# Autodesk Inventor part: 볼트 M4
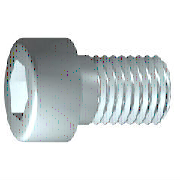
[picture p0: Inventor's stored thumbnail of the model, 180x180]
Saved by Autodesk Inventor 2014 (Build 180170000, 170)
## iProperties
IsCustomPart: 1
Created: 2012-02
Part Number: 볼트 M4
Material: 강철, 연강
Description: 6각머리 태핑 나사
Document SubType Name: Modeling
Standard: KS B 1003
Designer: mduedu
Standards Organization: KS
Language: ko-KR
Size Designation: M 4 x 10
Categories: <MemberInstance><Categories><Category DisplayName="조임쇠" InternalName="e4da775c-781d-43d5-af7c-5136215cf5a6" Mnemonic="FSTN"><Category DisplayName="볼트" InternalN
Density: 7.86 g/cm^3
Mass: 2.0371 g
Surface Area: 3.0572 cm^2
Volume: 0.259174 cm^3
Appearance: 강철
Author: mduedu
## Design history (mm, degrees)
sketch "스케치1"
  geometry: L1 (-1, 0)-(10, 0); L2 (10, 0)-(10, 2); L3 (10, 2)-(1.75, 2); L4 (1.75, 2)-(1.32, 2); L5 (1.32, 2)-(0, 2); L6 (0, 2)-(0, 3.5); L7 (0, 3.5)-(-4, 3.5); L8 (-4, 3.5)-(-4, 1.732); L9 (-4, 1.732)-(-2, 1.732); L10 (-2, 1.732)-(-1, 0); L11 (-6.8, 0)-(12.8, 0) reference; L12 (0, -0.7)-(0, 4.2) reference; L13 (1.75, 2)-(0, 2)
  constraints: 22 end point, 6 parallel, 2 collinear, 2 perpendicular, 1 horizontal, 1 point on line
  dimensions: "d1" = 8.25 distance from line of L3.end L2 (= GEL); "d2" = 0.42952 distance of L4.end L3.end (computed from GAL); "d3" = 4 distance between parallel lines of L8 L6 (= KOH); "d4" = 2 distance of L8.end L9.end (= INTI); "d5" = 60 deg angle of L10 L1; "d6" = 4 diameter of L3 L1 (= GD); "d7" = 4 diameter of L5 L1 (= BDM); "d8" = 3.4641 diameter of L9 L1 (= 1.1547 x SW); "d9" = 7 diameter of L7 L1 (= KOD); "d26" = 10 distance between parallel lines of L12 L2 (= NLG)
revolve "본체" sketch "스케치1" stored, may be unused: angle "d10" = 90 deg
sketch "스케치2"
  geometry: L1 (0, -4.9)-(0, 4.9) reference; L2 (-4.9, 0)-(4.9, 0) reference; L3 (1.732, 0)-(0.866, -1.5); L4 (0.866, -1.5)-(-0.866, -1.5); L5 (-0.866, -1.5)-(-1.732, 0); L6 (-1.732, 0)-(-0.866, 1.5); L7 (-0.866, 1.5)-(0.866, 1.5); L8 (0.866, 1.5)-(1.732, 0); 2 further points
  constraints: 12 end point, 1 coincident, 1 horizontal alignment, 1 point on line, 12 other
extrude "슬롯" join sketch "스케치2" stored distance "d11" = 10; taper "d12" = 0 deg
workplane "Work Plane1"
fillet "Fillet2" dims "d30" = 0.1 (= R)
body "Solid1"
fillet "모깎기1" dims "d17" = 0.4 (= RR)
feature "스레드" dims "d13" = 8.25 (= GEL), "d14" = 0
chamfer "모따기1" distance "d15" = 0.42941 (= -0.5 x SPD + 0.5 x GD); stored, may be unused: second distance "d16" = 0.42941 (= GUL), angle "d27" = 45 deg
other parameters: "GD" = 4 (= NND) [user parameter; used in 2 equation terms], "NLG" = 10 [user parameter; used in 1 equation term], "GEL" = 8.25 [user parameter; used in 2 equation terms], "KOD" = 7 [user parameter; used in 1 equation term], "KOH" = 4 [user parameter; used in 1 equation term], "INTI" = 2 [user parameter; used in 1 equation term], "GAL" = 0.42941 (= 0.61345 x PTC) [user parameter; used in 1 equation term], "GUL" = 0.42941 (= 0.61345 x PTC) [user parameter; used in 1 equation term], "BDM" = 4 (= NND) [user parameter; used in 1 equation term], "SW" = 3 [user parameter; used in 2 equation terms], "RR" = 0.4 [user parameter; used in 1 equation term], "SPD" = 3.14117 (= NND - 1.2269 x PTC) [user parameter; used in 1 equation term], "d19" = 0, "d28" = 0, "d29" = 0, "R" = 0.1 [user parameter; used in 1 equation term], "PHH" = 0.2 [user parameter], "GD1" = 3.14117 (= THREADDIA - 1.2269 x PTC) [user parameter], "THREADDIA" = 4 [user parameter; used in 1 equation term], "FAWI" = 45 deg [user parameter], "TPU" = 14.28571 (computed from PTC) [user parameter], "PTC" = 0.7 [user parameter; used in 5 equation terms], "NND" = 4 [user parameter; used in 3 equation terms], "TOA" = 30 deg [user parameter], "E0" = 3.465 (= 1.155 x SW) [user parameter]
